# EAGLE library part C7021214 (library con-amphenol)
AMPHENOL CONNECTOR
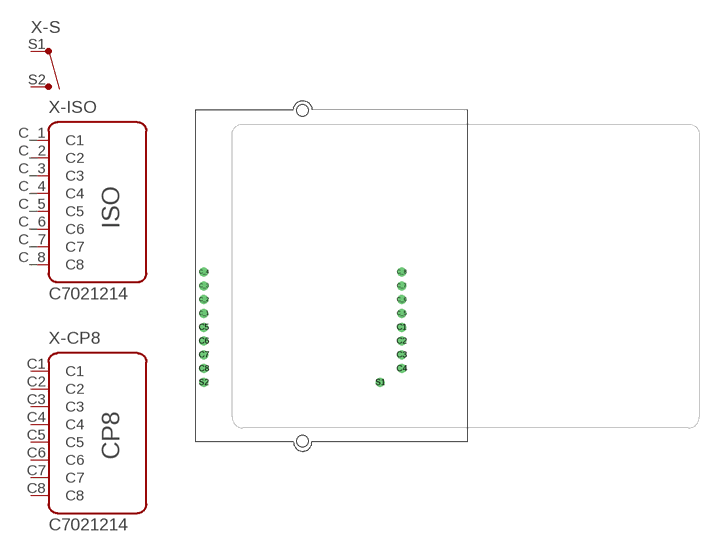
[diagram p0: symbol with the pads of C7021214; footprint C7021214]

Designator prefix X; gates -S=S -ISO=ISO8 -CP8=CP8

## C7021214 (OC_FARNELL: unknown; OC_NEWARK: unknown)  [C7021214]
C1  -CP8:C1  pas
C2  -CP8:C2  pas
C3  -CP8:C3  pas
C4  -CP8:C4  pas
C5  -CP8:C5  pas
C6  -CP8:C6  pas
C7  -CP8:C7  pas
C8  -CP8:C8  pas
C_1  -ISO:C1  pas
C_2  -ISO:C2  pas
C_3  -ISO:C3  pas
C_4  -ISO:C4  pas
C_5  -ISO:C5  pas
C_6  -ISO:C6  pas
C_7  -ISO:C7  pas
C_8  -ISO:C8  pas
S1  -S:S1  pas
S2  -S:S2  pas

## Footprint C7021214 (pad centres in mm)
AMPHENOL CONNECTOR
drill 1.1 round: C1 18.2,-9.46; C2 18.2,-12; C3 18.2,-14.54; C4 18.2,-17.08; C5 -18.2,-9.46; C6 -18.2,-12; C7 -18.2,-14.54; C8 -18.2,-17.08; C_1 -18.2,-6.92; C_2 -18.2,-4.38; C_3 -18.2,-1.84; C_4 -18.2,0.7; C_5 18.2,-6.92; C_6 18.2,-4.38; C_7 18.2,-1.84; C_8 18.2,0.7; S1 14.3,-19.62; S2 -18.2,-19.62
hole 2.1 at 0,-30.45
hole 2.1 at 0,30.45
